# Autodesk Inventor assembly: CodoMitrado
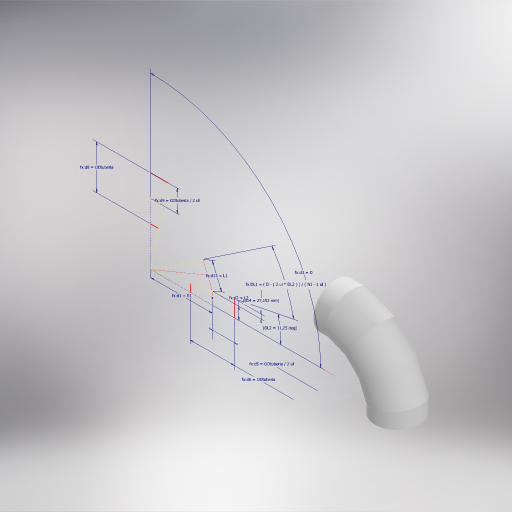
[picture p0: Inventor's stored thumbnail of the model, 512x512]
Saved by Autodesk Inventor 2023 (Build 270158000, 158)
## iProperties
RuleStatus: InUse
Created: 2023-01
Part Number: CodoMitrado
Document SubType Name: Assembly
Designer: Nelson C Agudelo A
L2: 75,786 mm
L1: 151,571 mm
Espesor: 2,500 mm
ODtuberia: 273,000 mm
N1: 4,000 ul
E1: 381,000 mm
D: 90,00 deg
Recorte: 27,152 mm
Author: Nelson C Agudelo A
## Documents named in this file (4)
- C:\Users\Camilo\OneDrive\Documents\09-Proyectos Inventor 2023\02-CodoMitrado\CodoMitrado.iam
- C:\Users\Camilo\OneDrive\Documents\09-Proyectos Inventor 2023\02-CodoMitrado\02-L2.ipt
- C:\Users\Camilo\OneDrive\Documents\09-Proyectos Inventor 2023\02-CodoMitrado\03-L1.ipt
- C:\Users\Camilo\OneDrive\Documents\09-Proyectos Inventor 2023\02-CodoMitrado\01-Esquema Codo Mitrado.ipt
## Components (6 placed, 3 different names)
1. 02-L2:1 — Mate:3, Flush:2, Flush:3, Mate:4, Flush:5, Mate:6
2. 02-L2:2 — Mate:4, Flush:4, Mate:6
3. 01-Esquema Codo Mitrado:1 — Mate:7
4. 03-L1:1 — Mate:3, Flush:2, Flush:3
5. 03-L1:2
6. 03-L1:3
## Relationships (8: Mate 4, Flush 4)
- Mate:3: 02-L2:1 ↔ 03-L1:1
- Flush:2: 02-L2:1 ↔ 03-L1:1
- Flush:3: 02-L2:1 ↔ 03-L1:1
- Mate:4: 02-L2:1 ↔ 02-L2:2
- Flush:4: 02-L2:2
- Flush:5: 02-L2:1
- Mate:6: 02-L2:1 ↔ 02-L2:2
- Mate:7: 01-Esquema Codo Mitrado:1
